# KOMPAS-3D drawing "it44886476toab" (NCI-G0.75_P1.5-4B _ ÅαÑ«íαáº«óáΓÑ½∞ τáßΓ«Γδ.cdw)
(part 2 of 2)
  Кривая без истории:10763
  Кривая без истории:10764
  Кривая без истории:10765
  Кривая без истории:10766
  Кривая без истории:10767
  Кривая без истории:10768
  Кривая без истории:10769
  Кривая без истории:10770
  Кривая без истории:10771
  Кривая без истории:10772
  Кривая без истории:10773
  Кривая без истории:10774
  Кривая без истории:10775
  Кривая без истории:10776
  Кривая без истории:10777
  Кривая без истории:10778
  Кривая без истории:10779
  Кривая без истории:10780
  Кривая без истории:10781
  Кривая без истории:10782
  Кривая без истории:10783
  Кривая без истории:10784
  Кривая без истории:10785
  Кривая без истории:10786
  Кривая без истории:10787
  Кривая без истории:10788
  Кривая без истории:10789
  Кривая без истории:10790
  Кривая без истории:10791
  Кривая без истории:10792
  Кривая без истории:10793
  Кривая без истории:10794
  Кривая без истории:10795
  Кривая без истории:10796
  Кривая без истории:10797
  Кривая без истории:10798
  Кривая без истории:10799
  Кривая без истории:10800
  Кривая без истории:10801
  Кривая без истории:10802
  Кривая без истории:10803
  Кривая без истории:10804
  Кривая без истории:10805
  Кривая без истории:10806
  Кривая без истории:10807
  Кривая без истории:10808
  Кривая без истории:10809
  Кривая без истории:10810
  Кривая без истории:10811
  Кривая без истории:10812
  Кривая без истории:10813
  Кривая без истории:10814
  Кривая без истории:10815
  Кривая без истории:10816
  Кривая без истории:10817
  Кривая без истории:10818
  Кривая без истории:10819
  Кривая без истории:10820
  Кривая без истории:10821
  Кривая без истории:10822
  Кривая без истории:10823
  Кривая без истории:10824
  Кривая без истории:10825
  Кривая без истории:10826
  Кривая без истории:10827
  Кривая без истории:10828
  Кривая без истории:10829
  Кривая без истории:10830
  Кривая без истории:10831
  Кривая без истории:10832
  Кривая без истории:10833
  Кривая без истории:10834
  Кривая без истории:10835
  Кривая без истории:10836
  Кривая без истории:10837
  Кривая без истории:10838
  Кривая без истории:10839
  Кривая без истории:10840
  Кривая без истории:10841
  Кривая без истории:10842
  Кривая без истории:10843
  Кривая без истории:10844
  Кривая без истории:10845
  Кривая без истории:10846
  Кривая без истории:10847
  Кривая без истории:10848
  Кривая без истории:10849
  Кривая без истории:10850
  Кривая без истории:10851
  Кривая без истории:10852
  Кривая без истории:10853
  Кривая без истории:10854
  Кривая без истории:10855
  Кривая без истории:10856
  Кривая без истории:10857
  Кривая без истории:10858
  Кривая без истории:10859
  Кривая без истории:10860
  Кривая без истории:10861
  Кривая без истории:10862
  Кривая без истории:10863
  Кривая без истории:10864
  Кривая без истории:10865
  Кривая без истории:10866
  Кривая без истории:10867
  Кривая без истории:10868
  Кривая без истории:10869
  Кривая без истории:10870
  Кривая без истории:10871
  Кривая без истории:10872
  Кривая без истории:10873
  Кривая без истории:10874
  Кривая без истории:10875
  Кривая без истории:10876
  Кривая без истории:10877
  Кривая без истории:10878
  Кривая без истории:10879
  Кривая без истории:10880
  Кривая без истории:10881
  Кривая без истории:10882
  Кривая без истории:10883
  Кривая без истории:10884
  Кривая без истории:10885
  Кривая без истории:10886
  Кривая без истории:10887
  Кривая без истории:10888
  Кривая без истории:10889
  Кривая без истории:10890
  Кривая без истории:10891
  Кривая без истории:10892
  Кривая без истории:10893
  Кривая без истории:10894
  Кривая без истории:10895
  Кривая без истории:10896
  Кривая без истории:10897
  Кривая без истории:10898
  Кривая без истории:10899
  Кривая без истории:10900
  Кривая без истории:10901
  Кривая без истории:10902
  Кривая без истории:10903
  Кривая без истории:10904
  Кривая без истории:10905
  Кривая без истории:10906
  Кривая без истории:10907
  Кривая без истории:10908
  Кривая без истории:10909
  Кривая без истории:10910
  Кривая без истории:10911
  Кривая без истории:10912
  Кривая без истории:10913
  Кривая без истории:10914
  Кривая без истории:10915
  Кривая без истории:10916
  Кривая без истории:10917
  Кривая без истории:10918
  Кривая без истории:10919
  Кривая без истории:10920
  Кривая без истории:10921
  Кривая без истории:10922
  Кривая без истории:10923
  Кривая без истории:10924
  Кривая без истории:10925
  Кривая без истории:10926
  Кривая без истории:10927
  Кривая без истории:10928
  Кривая без истории:10929
  Кривая без истории:10930
  Кривая без истории:10931
  Кривая без истории:10932
  Кривая без истории:10933
  Кривая без истории:10934
  Кривая без истории:10935
  Кривая без истории:10936
  Кривая без истории:10937
  Кривая без истории:10938
  Кривая без истории:10939
  Кривая без истории:10940
  Кривая без истории:10941
  Кривая без истории:10942
  Кривая без истории:10943
  Кривая без истории:10944
  Кривая без истории:10945
  Кривая без истории:10946
  Кривая без истории:10947
  Кривая без истории:10948
  Кривая без истории:10949
  Кривая без истории:10950
  Кривая без истории:10951
  Кривая без истории:10952
  Кривая без истории:10953
  Кривая без истории:10954
  Кривая без истории:10955
  Кривая без истории:10956
  Кривая без истории:10957
  Кривая без истории:10958
  Кривая без истории:10959
  Кривая без истории:10960
  Кривая без истории:10961
  Кривая без истории:10962
  Кривая без истории:10963
  Кривая без истории:10964
  Кривая без истории:10965
  Кривая без истории:10966
  Кривая без истории:10967
  Кривая без истории:10968
  Кривая без истории:10969
  Кривая без истории:10970
  Кривая без истории:10971
  Кривая без истории:10972
  Кривая без истории:10973
  Кривая без истории:10974
  Кривая без истории:10975
  Кривая без истории:10976
  Кривая без истории:10977
  Кривая без истории:10978
  Кривая без истории:10979
  Кривая без истории:10980
  Кривая без истории:10981
  Кривая без истории:10982
  Кривая без истории:10983
  Кривая без истории:10984
  Кривая без истории:10985
  Кривая без истории:10986
  Кривая без истории:10987
  Кривая без истории:10988
  Кривая без истории:10989
  Кривая без истории:10990
  Кривая без истории:10991
  Кривая без истории:10992
  Кривая без истории:10993
  Кривая без истории:10994
  Кривая без истории:10995
  Кривая без истории:10996
  Кривая без истории:10997
  Кривая без истории:10998
  Кривая без истории:10999
  Кривая без истории:11000
  Кривая без истории:11001
  Кривая без истории:11002
  Кривая без истории:11003
  Кривая без истории:11004
  Кривая без истории:11005
  Кривая без истории:11006
  Кривая без истории:11007
  Кривая без истории:11008
  Кривая без истории:11009
  Кривая без истории:11010
  Кривая без истории:11011
  Кривая без истории:11012
  Кривая без истории:11013
  Кривая без истории:11014
  Кривая без истории:11015
  Кривая без истории:11016
  Кривая без истории:11017
  Кривая без истории:11018
  Кривая без истории:11019
  Кривая без истории:11020
  Кривая без истории:11021
  Кривая без истории:11022
  Кривая без истории:11023
  Кривая без истории:11024
  Кривая без истории:11025
  Кривая без истории:11026
  Кривая без истории:11027
  Кривая без истории:11028
  Кривая без истории:11029
  Кривая без истории:11030
  Кривая без истории:11031
  Кривая без истории:11032
  Кривая без истории:11033
  Кривая без истории:11034
  Кривая без истории:11035
  Кривая без истории:11036
  Кривая без истории:11037
  Кривая без истории:11038
  Кривая без истории:11039
  Кривая без истории:11040
  Кривая без истории:11041
  Кривая без истории:11042
  Кривая без истории:11043
  Кривая без истории:11044
  Кривая без истории:11045
  Кривая без истории:11046
  Кривая без истории:11047
  Кривая без истории:11048
  Кривая без истории:11049
  Кривая без истории:11050
  Кривая без истории:11051
  Кривая без истории:11052
  Кривая без истории:11053
  Кривая без истории:11054
  Кривая без истории:11055
  Кривая без истории:11056
  Кривая без истории:11057
  Кривая без истории:11058
  Кривая без истории:11059
  Кривая без истории:11060
  Кривая без истории:11061
  Кривая без истории:11062
  Кривая без истории:11063
  Кривая без истории:11064
  Кривая без истории:11065
  Кривая без истории:11066
  Кривая без истории:11067
  Кривая без истории:11068
  Кривая без истории:11069
  Кривая без истории:11070
  Кривая без истории:11071
  Кривая без истории:11072
  Кривая без истории:11073
  Кривая без истории:11074
  Кривая без истории:11075
  Кривая без истории:11076
  Кривая без истории:11077
  Кривая без истории:11078
  Кривая без истории:11079
  Кривая без истории:11080
  Кривая без истории:11081
  Кривая без истории:11082
  Кривая без истории:11083
  Кривая без истории:11084
  Кривая без истории:11085
  Кривая без истории:11086
  Кривая без истории:11087
  Кривая без истории:11088
  Кривая без истории:11089
  Кривая без истории:11090
  Кривая без истории:11091
  Кривая без истории:11092
  Кривая без истории:11093
  Кривая без истории:11094
  Кривая без истории:11095
  Кривая без истории:11096
  Кривая без истории:11097
  Кривая без истории:11098
  Кривая без истории:11099
  Кривая без истории:11100
  Кривая без истории:11101
  Кривая без истории:11102
  Кривая без истории:11103
  Кривая без истории:11104
  Кривая без истории:11105
  Кривая без истории:11106
  Кривая без истории:11107
  Кривая без истории:11108
  Кривая без истории:11109
  Кривая без истории:11110
  Кривая без истории:11111
  Кривая без истории:11112
  Кривая без истории:11113
  Кривая без истории:11114
  Кривая без истории:11115
  Кривая без истории:11116
  Кривая без истории:11117
  Кривая без истории:11118
  Кривая без истории:11119
  Кривая без истории:11120
  Кривая без истории:11121
  Кривая без истории:11122
  Кривая без истории:11123
  Кривая без истории:11124
  Кривая без истории:11125
  Кривая без истории:11126
  Кривая без истории:11127
  Кривая без истории:11128
  Кривая без истории:11129
  Кривая без истории:11130
  Кривая без истории:11131
  Кривая без истории:11132
  Кривая без истории:11133
  Кривая без истории:11134
  Кривая без истории:11135
  Кривая без истории:11136
  Кривая без истории:11137
  Кривая без истории:11138
  Кривая без истории:11139
  Кривая без истории:11140
  Кривая без истории:11141
  Кривая без истории:11142
  Кривая без истории:11143
  Кривая без истории:11144
  Кривая без истории:11145
  Кривая без истории:11146
  Кривая без истории:11147
  Кривая без истории:11148
  Кривая без истории:11149
  Кривая без истории:11150
  Кривая без истории:11151
  Кривая без истории:11152
  Кривая без истории:11153
  Кривая без истории:11154
  Кривая без истории:11155
  Кривая без истории:11156
  Кривая без истории:11157
  Кривая без истории:11158
  Кривая без истории:11159
  Кривая без истории:11160
  Кривая без истории:11161
  Кривая без истории:11162
  Кривая без истории:11163
  Кривая без истории:11164
  Кривая без истории:11165
  Кривая без истории:11166
  Кривая без истории:11167
  Кривая без истории:11168
  Кривая без истории:11169
  Кривая без истории:11170
  Кривая без истории:11171
  Кривая без истории:11172
  Кривая без истории:11173
  Кривая без истории:11174
  Кривая без истории:11175
  Кривая без истории:11176
  Кривая без истории:11177
  Кривая без истории:11178
  Кривая без истории:11179
  Кривая без истории:11180
  Кривая без истории:11181
  Кривая без истории:11182
  Кривая без истории:11183
  Кривая без истории:11184
  Кривая без истории:11185
  Кривая без истории:11186
  Кривая без истории:11187
  Кривая без истории:11188
  Кривая без истории:11189
  Кривая без истории:11190
  Кривая без истории:11191
  Кривая без истории:11192
  Кривая без истории:11193
  Кривая без истории:11194
  Кривая без истории:11195
  Кривая без истории:11196
  Кривая без истории:11197
  Кривая без истории:11198
  Кривая без истории:11199
  Кривая без истории:11200
  Кривая без истории:11201
  Кривая без истории:11202
  Кривая без истории:11203
  Кривая без истории:11204
  Кривая без истории:11205
  Кривая без истории:11206
  Кривая без истории:11207
  Кривая без истории:11208
  Кривая без истории:11209
  Кривая без истории:11210
  Кривая без истории:11211
  Кривая без истории:11212
  Кривая без истории:11213
  Кривая без истории:11214
  Кривая без истории:11215
  Кривая без истории:11216
  Кривая без истории:11217
  Кривая без истории:11218
  Кривая без истории:11219
  Кривая без истории:11220
  Кривая без истории:11221
  Кривая без истории:11222
  Кривая без истории:11223
  Кривая без истории:11224
  Кривая без истории:11225
  Кривая без истории:11226
  Кривая без истории:11227
  Кривая без истории:11228
  Кривая без истории:11229
  Кривая без истории:11230
  Кривая без истории:11231
  Кривая без истории:11232
  Кривая без истории:11233
  Кривая без истории:11234
  Кривая без истории:11235
  Кривая без истории:11236
  Кривая без истории:11237
  Кривая без истории:11238
  Кривая без истории:11239
  Кривая без истории:11240
  Кривая без истории:11241
  Кривая без истории:11242
  Кривая без истории:11243
  Кривая без истории:11244
  Кривая без истории:11245
  Кривая без истории:11246
  Кривая без истории:11247
  Кривая без истории:11248
  Кривая без истории:11249
  Кривая без истории:11250
  Кривая без истории:11251
  Кривая без истории:11252
  Кривая без истории:11253
  Кривая без истории:11254
  Кривая без истории:11255
  Кривая без истории:11256
  Кривая без истории:11257
  Кривая без истории:11258
  Кривая без истории:11259
  Кривая без истории:11260
  Кривая без истории:11261
  Кривая без истории:11262
  Кривая без истории:11263
  Кривая без истории:11264
  Кривая без истории:11265
  Кривая без истории:11266
  Кривая без истории:11267
  Кривая без истории:11268
  Кривая без истории:11269
  Кривая без истории:11270
  Кривая без истории:11271
  Кривая без истории:11272
  Кривая без истории:11273
  Кривая без истории:11274
  Кривая без истории:11275
  Кривая без истории:11276
  Кривая без истории:11277
  Кривая без истории:11278
  Кривая без истории:11279
  Кривая без истории:11280
  Кривая без истории:11281
  Кривая без истории:11282
  Кривая без истории:11283
  Кривая без истории:11284
  Кривая без истории:11285
  Кривая без истории:11286
  Кривая без истории:11287
  Кривая без истории:11288
  Кривая без истории:11289
  Кривая без истории:11290
  Кривая без истории:11291
  Кривая без истории:11292
  Кривая без истории:11293
  Кривая без истории:11294
  Кривая без истории:11295
  Кривая без истории:11296
  Кривая без истории:11297
  Кривая без истории:11298
  Кривая без истории:11299
  Кривая без истории:11300
  Кривая без истории:11301
  Кривая без истории:11302
  Кривая без истории:11303
  Кривая без истории:11304
  Кривая без истории:11305
  Кривая без истории:11306
  Кривая без истории:11307
  Кривая без истории:11308
  Кривая без истории:11309
  Кривая без истории:11310
  Кривая без истории:11311
  Кривая без истории:11312
  Кривая без истории:11313
  Кривая без истории:11314
  Кривая без истории:11315
  Кривая без истории:11316
  Кривая без истории:11317
  Кривая без истории:11318
  Кривая без истории:11319
  Кривая без истории:11320
  Кривая без истории:11321
  Кривая без истории:11322
  Кривая без истории:11323
  Кривая без истории:11324
  Кривая без истории:11325
  Кривая без истории:11326
  Кривая без истории:11327
  Кривая без истории:11328
  Кривая без истории:11329
  Кривая без истории:11330
  Кривая без истории:11331
  Кривая без истории:11332
  Кривая без истории:11333
  Кривая без истории:11334
  Кривая без истории:11335
  Кривая без истории:11336
  Кривая без истории:11337
  Кривая без истории:11338
  Кривая без истории:11339
  Кривая без истории:11340
  Кривая без истории:11341
  Кривая без истории:11342
  Кривая без истории:11343
  Кривая без истории:11344
  Кривая без истории:11345
  Кривая без истории:11346
  Кривая без истории:11347
  Кривая без истории:11348
  Кривая без истории:11349
  Кривая без истории:11350
  Кривая без истории:11351
  Кривая без истории:11352
  Кривая без истории:11353
  Кривая без истории:11354
  Кривая без истории:11355
  Кривая без истории:11356
  Кривая без истории:11357
  Кривая без истории:11358
  Кривая без истории:11359
  Кривая без истории:11360
  Кривая без истории:11361
  Кривая без истории:11362
  Кривая без истории:11363
  Кривая без истории:11364
  Кривая без истории:11365
  Кривая без истории:11366
  Кривая без истории:11367
  Кривая без истории:11368
  Кривая без истории:11369
  Кривая без истории:11370
  Кривая без истории:11371
  Кривая без истории:11372
  Кривая без истории:11373
  Кривая без истории:11374
  Кривая без истории:11375
  Кривая без истории:11376
  Кривая без истории:11377
  Кривая без истории:11378
  Кривая без истории:11379
  Кривая без истории:11380
  Кривая без истории:11381
  Кривая без истории:11382
  Кривая без истории:11383
  Кривая без истории:11384
  Кривая без истории:11385
  Кривая без истории:11386
  Кривая без истории:11387
  Кривая без истории:11388
  Кривая без истории:11389
  Кривая без истории:11390
  Кривая без истории:11391
  Кривая без истории:11392
  Кривая без истории:11393
  Кривая без истории:11394
  Кривая без истории:11395
  Кривая без истории:11396
  Кривая без истории:11397
  Кривая без истории:11398
  Кривая без истории:11399
  Кривая без истории:11400
  Кривая без истории:11401
  Кривая без истории:11402
  Кривая без истории:11403
  Кривая без истории:11404
  Кривая без истории:11405
  Кривая без истории:11406
  Кривая без истории:11407
  Кривая без истории:11408
  Кривая без истории:11409
  Кривая без истории:11410
  Кривая без истории:11411
  Кривая без истории:11412
  Кривая без истории:11413
  Кривая без истории:11414
  Кривая без истории:11415
  Кривая без истории:11416
  Кривая без истории:11417
  Кривая без истории:11418
  Кривая без истории:11419
  Кривая без истории:11420
  Кривая без истории:11421
  Кривая без истории:11422
  Кривая без истории:11423
  Кривая без истории:11424
  Кривая без истории:11425
  Кривая без истории:11426
  Кривая без истории:11427
  Кривая без истории:11428
  Кривая без истории:11429
  Кривая без истории:11430
  Кривая без истории:11431
  Кривая без истории:11432
  Кривая без истории:11433
  Кривая без истории:11434
  Кривая без истории:11435
  Кривая без истории:11436
  Кривая без истории:11437
  Кривая без истории:11438
  Кривая без истории:11439
  Кривая без истории:11440
  Кривая без истории:11441
  Кривая без истории:11442
  Кривая без истории:11443
  Кривая без истории:11444
  Кривая без истории:11445
  Кривая без истории:11446
  Кривая без истории:11447
  Кривая без истории:11448
  Кривая без истории:11449
  Кривая без истории:11450
  Кривая без истории:11451
  Кривая без истории:11452
  Кривая без истории:11453
  Кривая без истории:11454
  Кривая без истории:11455
  Кривая без истории:11456
  Кривая без истории:11457
  Кривая без истории:11458
  Кривая без истории:11459
  Кривая без истории:11460
  Кривая без истории:11461
  Кривая без истории:11462
  Кривая без истории:11463
  Кривая без истории:11464
  Кривая без истории:11465
  Кривая без истории:11466
  Кривая без истории:11467
  Кривая без истории:11468
  Кривая без истории:11469
  Кривая без истории:11470
  Кривая без истории:11471
  Кривая без истории:11472
  Кривая без истории:11473
  Кривая без истории:11474
  Кривая без истории:11475
  Кривая без истории:11476
  Кривая без истории:11477
  Кривая без истории:11478
  Кривая без истории:11479
  Кривая без истории:11480
  Кривая без истории:11481
  Кривая без истории:11482
  Кривая без истории:11483
  Кривая без истории:11484
  Кривая без истории:11485
  Кривая без истории:11486
  Кривая без истории:11487
  Кривая без истории:11488
  Кривая без истории:11489
  Кривая без истории:11490
  Кривая без истории:11491
  Кривая без истории:11492
  Кривая без истории:11493
  Кривая без истории:11494
  Кривая без истории:11495
  Кривая без истории:11496
  Кривая без истории:11497
  Кривая без истории:11498
  Кривая без истории:11499
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Dimensions and other numbers on the sheet: 4±1; 1:1; 1; 13.01.25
